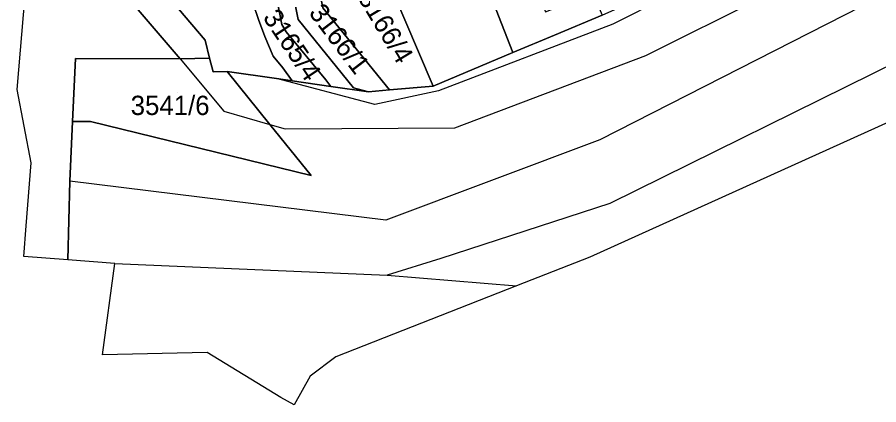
# Model space of a CAD drawing. Extents: x -262657 to -261595, y -1238015 to -1237156.
# Drawn here: x -262001.2 to -261911.9, y -1238015.1 to -1237974.9 of the extents above; entities that cross this region are included whole.
import ezdxf

# ---------------------------------------------------------------- set-up
doc = ezdxf.new("R2010")
doc.units = 0
for name, color, linetype in [('body_kn', 7, 'Continuous'), ('kladpar_druhypozemkov', 7, 'Continuous'), ('kladpar_hranice', 7, 'Continuous'), ('kladpar_parcelnecisla', 7, 'Continuous'), ('kladpar_plochy', 7, 'Continuous'), ('zappar_hrandruhpozemk', 7, 'Continuous')]:
    doc.layers.add(name, color=color, linetype=linetype)

msp = doc.modelspace()

# ---------------------------------------------------------------- linework, layer by layer
at = {"layer": 'body_kn'}
for p, q in [((-261976.22, -1237975.18), (-261976.22, -1237975.18)), ((-261973.8, -1237975.69), (-261973.8, -1237975.69)), ((-261972.11, -1237975.17), (-261972.11, -1237975.17)), ((-261972.11, -1237975.17), (-261972.11, -1237975.17)), ((-261939.48, -1237975.65), (-261939.48, -1237975.65)), ((-261973.34, -1237976.46), (-261973.34, -1237976.46)), ((-261981.76, -1237977.31), (-261981.76, -1237977.31)), ((-261975.56, -1237976.95), (-261975.56, -1237976.95)), ((-261945.53, -1237976.8), (-261945.53, -1237976.8)), ((-261995.19, -1237979.22), (-261995.19, -1237979.22)), ((-261984.32, -1237979.25), (-261984.32, -1237979.25)), ((-261984.32, -1237979.25), (-261984.32, -1237979.25)), ((-261981.28, -1237979.18), (-261981.28, -1237979.18)), ((-261974.69, -1237978.99), (-261974.69, -1237978.99)), ((-261949.86, -1237978.59), (-261949.86, -1237978.59)), ((-261949.86, -1237978.59), (-261949.86, -1237978.59)), ((-261936.04, -1237978.91), (-261936.04, -1237978.91)), ((-261973.7, -1237980.19), (-261973.7, -1237980.19)), ((-261980.92, -1237980.59), (-261980.92, -1237980.59)), ((-261979.48, -1237980.57), (-261979.48, -1237980.57)), ((-261979.48, -1237980.57), (-261979.48, -1237980.57)), ((-261974.34, -1237981.31), (-261974.34, -1237981.31)), ((-261972.72, -1237981.54), (-261972.72, -1237981.54)), ((-261969.24, -1237981.44), (-261969.24, -1237981.44)), ((-262001.23, -1237982.42), (-262001.23, -1237982.42)), ((-261968.73, -1237982.12), (-261968.73, -1237982.12)), ((-261966.36, -1237982.25), (-261966.36, -1237982.25)), ((-261964.82, -1237982.68), (-261964.82, -1237982.68)), ((-261962.63, -1237982.48), (-261962.63, -1237982.48)), ((-261962.63, -1237982.48), (-261962.63, -1237982.48)), ((-261958.11, -1237982.08), (-261958.11, -1237982.08)), ((-261957.54, -1237982.59), (-261957.54, -1237982.59)), ((-261979.82, -1237984.68), (-261979.82, -1237984.68)), ((-261964.16, -1237983.99), (-261964.16, -1237983.99)), ((-261995.49, -1237985.74), (-261995.49, -1237985.74)), ((-261995.49, -1237985.74), (-261995.49, -1237985.74)), ((-261993.65, -1237985.74), (-261993.65, -1237985.74)), ((-261975.03, -1237986.06), (-261975.03, -1237986.06)), ((-261975.03, -1237986.06), (-261975.03, -1237986.06)), ((-261955.87, -1237986.41), (-261955.87, -1237986.41)), ((-261973.44, -1237986.52), (-261973.44, -1237986.52)), ((-261940.81, -1237987.66), (-261940.81, -1237987.66)), ((-261999.77, -1237990.05), (-261999.77, -1237990.05)), ((-261970.74, -1237991.35), (-261970.74, -1237991.35)), ((-261995.78, -1237991.95), (-261995.78, -1237991.95)), ((-261939.78, -1237994.25), (-261939.78, -1237994.25)), ((-261963, -1237995.98), (-261963, -1237995.98)), ((-262000.3, -1237996.58), (-262000.3, -1237996.58)), ((-262000.55, -1237999.73), (-262000.55, -1237999.73)), ((-261941.87, -1237999.81), (-261941.87, -1237999.81)), ((-261996, -1238000.09), (-261996, -1238000.09)), ((-261991.11, -1238000.48), (-261991.11, -1238000.48)), ((-261991.11, -1238000.48), (-261991.11, -1238000.48)), ((-261957.3, -1237999.94), (-261957.3, -1237999.94)), ((-261962.88, -1238001.68), (-261962.88, -1238001.68)), ((-261949.48, -1238002.8), (-261949.48, -1238002.8)), ((-261981.54, -1238009.7), (-261981.54, -1238009.7)), ((-261992.4, -1238009.93), (-261992.4, -1238009.93)), ((-261968.18, -1238010.15), (-261968.18, -1238010.15)), ((-261970.85, -1238012.16), (-261970.85, -1238012.16)), ((-261973.89, -1238014.34), (-261973.89, -1238014.34)), ((-261972.53, -1238015.11), (-261972.53, -1238015.11))]:
    msp.add_line(p, q, dxfattribs=at)
at = {"layer": 'kladpar_druhypozemkov'}
for p, q in [((-261974.9, -1237975.2), (-261974.9, -1237975.2)), ((-261984.63, -1237982.73), (-261984.63, -1237982.73))]:
    msp.add_line(p, q, dxfattribs=at)
at = {"layer": 'kladpar_hranice'}
for points in [[(-261989.52, -1237897.17), (-261989.7, -1237902.51), (-261990.17, -1237916.28), (-261991.69, -1237955.34), (-261990.98, -1237971.5), (-261984.32, -1237979.25), (-261995.19, -1237979.22), (-261995.49, -1237985.74), (-261995.78, -1237991.95), (-261996, -1238000.09), (-262000.55, -1237999.73), (-262000.3, -1237996.58), (-261999.77, -1237990.05), (-262001.23, -1237982.42), (-261996.13, -1237922.1), (-261993.79, -1237887.01)], [(-261989.7, -1237902.51), (-261987.65, -1237906.07), (-261986.33, -1237905.88), (-261986.5, -1237920.87), (-261990.4, -1237967.07), (-261988.07, -1237969.83), (-261986.48, -1237971.71), (-261981.76, -1237977.31), (-261981.28, -1237979.18), (-261984.32, -1237979.25), (-261990.98, -1237971.5), (-261991.69, -1237955.34), (-261990.17, -1237916.28), (-261989.7, -1237902.51)], [(-261727.99, -1237912.57), (-261763.54, -1237924.41), (-261786.15, -1237931.76), (-261793.04, -1237934.21), (-261822.63, -1237945.17), (-261832.88, -1237949.98), (-261834.67, -1237950.82), (-261857.62, -1237961.58), (-261876.1, -1237970.13), (-261879.42, -1237971.62), (-261885.86, -1237974.51), (-261889.63, -1237976.21), (-261941.87, -1237999.81), (-261949.48, -1238002.8), (-261968.18, -1238010.15), (-261970.85, -1238012.16), (-261972.53, -1238015.11), (-261973.89, -1238014.34), (-261981.54, -1238009.7), (-261992.4, -1238009.93), (-261991.11, -1238000.48), (-261996, -1238000.09), (-261995.78, -1237991.95), (-261995.49, -1237985.74)], [(-261949.86, -1237978.59), (-261958.31, -1237956.92), (-261960.29, -1237951.4), (-261960.61, -1237950.64), (-261951.95, -1237947.03), (-261947.43, -1237957.86), (-261953.91, -1237960.48), (-261950.76, -1237968.27), (-261949.19, -1237967.63), (-261946.45, -1237974.4), (-261941.55, -1237972.42), (-261940.58, -1237974.72), (-261945.53, -1237976.8), (-261949.86, -1237978.59)], [(-261949.86, -1237978.59), (-261958.11, -1237982.08), (-261965.51, -1237964.75), (-261969.76, -1237954.42), (-261963.53, -1237951.87), (-261960.61, -1237950.64), (-261960.29, -1237951.4), (-261958.31, -1237956.92), (-261949.86, -1237978.59)], [(-261978.06, -1237954.49), (-261976.62, -1237954.45), (-261976.4, -1237954.45), (-261977.47, -1237964.39), (-261977.47, -1237965.86), (-261977.35, -1237968.59), (-261977.18, -1237971.31), (-261976.79, -1237973.44), (-261976.22, -1237975.18), (-261975.56, -1237976.95), (-261974.69, -1237978.99), (-261973.7, -1237980.19), (-261972.72, -1237981.54), (-261974.34, -1237981.31), (-261979.48, -1237980.57), (-261980.92, -1237980.59), (-261981.28, -1237979.18), (-261981.76, -1237977.31), (-261986.48, -1237971.71), (-261985.7, -1237958.52), (-261984.96, -1237954.67), (-261978.06, -1237954.49)], [(-261974.66, -1237954.44), (-261974.8, -1237955.77), (-261975.79, -1237965.54), (-261975.33, -1237967.87), (-261973.8, -1237975.69), (-261973.34, -1237976.46), (-261969.24, -1237981.44), (-261968.73, -1237982.12), (-261972.72, -1237981.54), (-261973.7, -1237980.19), (-261974.69, -1237978.99), (-261975.56, -1237976.95), (-261976.22, -1237975.18), (-261976.79, -1237973.44), (-261977.18, -1237971.31), (-261977.35, -1237968.59), (-261977.47, -1237965.86), (-261977.47, -1237964.39), (-261976.4, -1237954.45), (-261974.66, -1237954.44)], [(-261972.11, -1237975.17), (-261966.36, -1237982.25), (-261964.82, -1237982.68), (-261968.73, -1237982.12), (-261969.24, -1237981.44), (-261973.34, -1237976.46), (-261973.8, -1237975.69), (-261975.33, -1237967.87), (-261975.79, -1237965.54), (-261974.8, -1237955.77), (-261974.66, -1237954.44), (-261973.03, -1237954.43), (-261974.03, -1237965.33), (-261973.66, -1237967.28), (-261972.11, -1237975.17)], [(-261979.48, -1237980.57), (-261974.34, -1237981.31), (-261972.72, -1237981.54), (-261968.73, -1237982.12), (-261964.82, -1237982.68), (-261962.63, -1237982.48), (-261958.11, -1237982.08), (-261949.86, -1237978.59), (-261945.53, -1237976.8), (-261940.58, -1237974.72), (-261934.78, -1237972.1), (-261933.2, -1237971.33), (-261927.07, -1237968.04), (-261924.43, -1237966.62), (-261913.53, -1237961.12), (-261907.03, -1237957.77)], [(-261962.63, -1237982.48), (-261969.54, -1237973.97), (-261971.02, -1237966.37), (-261967.74, -1237965.45), (-261965.51, -1237964.75), (-261958.11, -1237982.08), (-261962.63, -1237982.48)], [(-261973.66, -1237967.28), (-261971.52, -1237966.51), (-261971.02, -1237966.37), (-261969.54, -1237973.97), (-261962.63, -1237982.48), (-261964.82, -1237982.68), (-261966.36, -1237982.25), (-261972.11, -1237975.17), (-261973.66, -1237967.28)], [(-261995.49, -1237985.74), (-261995.19, -1237979.22), (-261984.32, -1237979.25)], [(-261984.32, -1237979.25), (-261981.28, -1237979.18), (-261980.92, -1237980.59), (-261979.48, -1237980.57)], [(-261995.49, -1237985.74), (-261993.65, -1237985.74), (-261970.74, -1237991.35), (-261975.03, -1237986.06), (-261979.48, -1237980.57)], [(-261979.48, -1237980.57), (-261975.03, -1237986.06), (-261970.74, -1237991.35), (-261993.65, -1237985.74), (-261995.49, -1237985.74)]]:
    msp.add_lwpolyline(points, dxfattribs=at)
at = {"layer": 'kladpar_plochy'}
for points in [[(-261989.52, -1237897.17), (-261989.7, -1237902.51), (-261990.17, -1237916.28), (-261991.69, -1237955.34), (-261990.98, -1237971.5), (-261984.32, -1237979.25), (-261995.19, -1237979.22), (-261995.49, -1237985.74), (-261995.78, -1237991.95), (-261996, -1238000.09), (-262000.55, -1237999.73), (-262000.3, -1237996.58), (-261999.77, -1237990.05), (-262001.23, -1237982.42), (-261996.13, -1237922.1), (-261993.79, -1237887.01)], [(-261889.63, -1237976.21), (-261941.87, -1237999.81), (-261949.48, -1238002.8), (-261968.18, -1238010.15), (-261970.85, -1238012.16), (-261972.53, -1238015.11), (-261973.89, -1238014.34), (-261981.54, -1238009.7), (-261992.4, -1238009.93), (-261991.11, -1238000.48), (-261996, -1238000.09), (-261995.78, -1237991.95), (-261995.49, -1237985.74), (-261993.65, -1237985.74), (-261970.74, -1237991.35), (-261975.03, -1237986.06), (-261979.48, -1237980.57), (-261974.34, -1237981.31), (-261972.72, -1237981.54), (-261968.73, -1237982.12), (-261964.82, -1237982.68), (-261962.63, -1237982.48), (-261958.11, -1237982.08), (-261949.86, -1237978.59), (-261945.53, -1237976.8), (-261940.58, -1237974.72)]]:
    msp.add_lwpolyline(points, dxfattribs=at)
for points in [[(-261989.7, -1237902.51), (-261987.65, -1237906.07), (-261986.33, -1237905.88), (-261986.5, -1237920.87), (-261990.4, -1237967.07), (-261988.07, -1237969.83), (-261986.48, -1237971.71), (-261981.76, -1237977.31), (-261981.28, -1237979.18), (-261984.32, -1237979.25), (-261990.98, -1237971.5), (-261991.69, -1237955.34), (-261990.17, -1237916.28)], [(-261949.86, -1237978.59), (-261958.31, -1237956.92), (-261960.29, -1237951.4), (-261960.61, -1237950.64), (-261951.95, -1237947.03), (-261947.43, -1237957.86), (-261953.91, -1237960.48), (-261950.76, -1237968.27), (-261949.19, -1237967.63), (-261946.45, -1237974.4), (-261941.55, -1237972.42), (-261940.58, -1237974.72), (-261945.53, -1237976.8)], [(-261949.86, -1237978.59), (-261958.11, -1237982.08), (-261965.51, -1237964.75), (-261969.76, -1237954.42), (-261963.53, -1237951.87), (-261960.61, -1237950.64), (-261960.29, -1237951.4), (-261958.31, -1237956.92)], [(-261978.06, -1237954.49), (-261976.62, -1237954.45), (-261976.4, -1237954.45), (-261977.47, -1237964.39), (-261977.47, -1237965.86), (-261977.35, -1237968.59), (-261977.18, -1237971.31), (-261976.79, -1237973.44), (-261976.22, -1237975.18), (-261975.56, -1237976.95), (-261974.69, -1237978.99), (-261973.7, -1237980.19), (-261972.72, -1237981.54), (-261974.34, -1237981.31), (-261979.48, -1237980.57), (-261980.92, -1237980.59), (-261981.28, -1237979.18), (-261981.76, -1237977.31), (-261986.48, -1237971.71), (-261985.7, -1237958.52), (-261984.96, -1237954.67)], [(-261974.66, -1237954.44), (-261974.8, -1237955.77), (-261975.79, -1237965.54), (-261975.33, -1237967.87), (-261973.8, -1237975.69), (-261973.34, -1237976.46), (-261969.24, -1237981.44), (-261968.73, -1237982.12), (-261972.72, -1237981.54), (-261973.7, -1237980.19), (-261974.69, -1237978.99), (-261975.56, -1237976.95), (-261976.22, -1237975.18), (-261976.79, -1237973.44), (-261977.18, -1237971.31), (-261977.35, -1237968.59), (-261977.47, -1237965.86), (-261977.47, -1237964.39), (-261976.4, -1237954.45)], [(-261972.11, -1237975.17), (-261966.36, -1237982.25), (-261964.82, -1237982.68), (-261968.73, -1237982.12), (-261969.24, -1237981.44), (-261973.34, -1237976.46), (-261973.8, -1237975.69), (-261975.33, -1237967.87), (-261975.79, -1237965.54), (-261974.8, -1237955.77), (-261974.66, -1237954.44), (-261973.03, -1237954.43), (-261974.03, -1237965.33), (-261973.66, -1237967.28)], [(-261962.63, -1237982.48), (-261969.54, -1237973.97), (-261971.02, -1237966.37), (-261967.74, -1237965.45), (-261965.51, -1237964.75), (-261958.11, -1237982.08)], [(-261973.66, -1237967.28), (-261971.52, -1237966.51), (-261971.02, -1237966.37), (-261969.54, -1237973.97), (-261962.63, -1237982.48), (-261964.82, -1237982.68), (-261966.36, -1237982.25), (-261972.11, -1237975.17)], [(-261984.32, -1237979.25), (-261981.28, -1237979.18), (-261980.92, -1237980.59), (-261979.48, -1237980.57), (-261975.03, -1237986.06), (-261970.74, -1237991.35), (-261993.65, -1237985.74), (-261995.49, -1237985.74), (-261995.19, -1237979.22)]]:
    msp.add_lwpolyline(points, close=True, dxfattribs=at)
at = {"layer": 'zappar_hrandruhpozemk'}
for p, q in [((-261857.28, -1237934.4), (-261939.48, -1237975.65)), ((-261936.04, -1237978.91), (-261872.88, -1237947.3)), ((-261872.23, -1237952.67), (-261940.81, -1237987.66)), ((-261939.48, -1237975.65), (-261957.54, -1237982.59)), ((-261984.32, -1237979.25), (-261979.82, -1237984.68)), ((-261909.12, -1237979.11), (-261939.78, -1237994.25)), ((-261964.16, -1237983.99), (-261974.34, -1237981.31)), ((-261957.54, -1237982.59), (-261964.16, -1237983.99)), ((-261979.82, -1237984.68), (-261975.03, -1237986.06)), ((-261940.81, -1237987.66), (-261963, -1237995.98)), ((-261963, -1237995.98), (-261995.78, -1237991.95))]:
    msp.add_line(p, q, dxfattribs=at)
for points in [[(-261975.03, -1237986.06), (-261973.44, -1237986.52), (-261955.87, -1237986.41), (-261936.04, -1237978.91)], [(-261939.78, -1237994.25), (-261957.3, -1237999.94), (-261962.88, -1238001.68)], [(-261991.11, -1238000.48), (-261962.88, -1238001.68), (-261949.48, -1238002.8)]]:
    msp.add_lwpolyline(points, dxfattribs=at)

# ---------------------------------------------------------------- texts
at = {"layer": 'kladpar_parcelnecisla'}
for s, rotation, p in [('3166/4', 301, (-261965.977, -1237972.921)), ('3166/1', 307, (-261971.076, -1237974.501)), ('3165/4', 304, (-261975.83, -1237974.977))]:
    msp.add_text(s, height=2, rotation=rotation, dxfattribs=at).set_placement(p)
msp.add_text('3541/6', height=2, dxfattribs=at).set_placement((-261989.468, -1237985.08))

doc.saveas('drawing.dxf')
